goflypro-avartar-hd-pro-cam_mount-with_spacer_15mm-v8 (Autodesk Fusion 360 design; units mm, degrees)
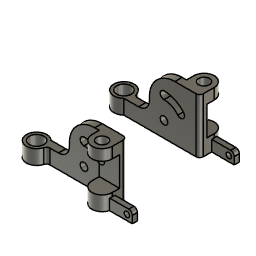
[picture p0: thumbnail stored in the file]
sketch "Skizze1" plane through (0, 0, 0) normal (0, 0, 1) x axis (1, 0, 0)
  line L1 (7.2, 0) -> (-7.2, 0)
  line L2 (7.2, 0) -> (7.2, -2)
  line L3 (-1, 0) -> (-1, 2)
  line L4 (12.8, 2) -> (-8.605, 2)
  line L5 (12.8, 2) -> (12.8, -2)
  line L6 (12.8, 0) -> (7.2, 0)
  line L7 (11, -2) -> (11, 2)
  line L8 (12.8, -2) -> (11, -2)
  circle C1 centre (-10, 0) radius 2
  circle C2 centre (10, -2) radius 1.5
  circle C3 centre (-10, 0) radius 2.8
  circle C4 centre (10, -2) radius 2.8
  point P6 (-7.2, 0)
  point P7 (7.2, -2)
  point P10 (-1, 0)
  point P12 (12.8, -2)
  point P14 (12.8, 0)
  point P15 (11, 2)
  concentric C1 C3
  concentric C2 C4
  coincident C3 P6
  horizontal L1
  coincident C4 P7
  tangent C4 L2
  perpendicular L1 L2
  perpendicular L1 L3
  coincident L1 P10
  coincident C4 P12
  tangent C4 L5
  perpendicular L4 L5
  midpoint L5 P14
  coincident L4 P15
  perpendicular L6 L7
  dimension "d1" diameter C1 = 4
  dimension "d2" diameter C2 = 3
  dimension "d3" diameter C3 = 5.6
  dimension "d4" diameter C4 = 5.6
extrude "Extrusion1" new body sketch "Skizze1" profile of C1 C3 L1 L3 L4 along normal blind 4 bodies "GoFlyPro - Avatar-HD-Pro-cam mount with spacer 15mm - left"
extrude "Extrusion5" new body sketch "Skizze1" profile of C2 C4 L2 L5 L6 L7 L8 along normal blind 4
extrude "Extrusion8" add sketch "Skizze1" profile of C4 L1 L3 L4 L5 L6 L7 along normal blind 15
sketch "Skizze2" plane through (0, 0, 0) normal (0, 1, 0) x axis (1, 0, 0)
  line L1 (7.2, 0) -> (-1, 0)
  line L2 (7.2, -4) -> (7.2, 0)
  line L3 (7.2, -15) -> (7.2, -4)
  line L4 (-1, -15) -> (7.2, -15)
  line L5 (-1, 0) -> (-1, -15)
  circle C1 centre (3, -4.25) radius 1.05
  circle C2 centre (3, -4.25) radius 4.95
  circle C3 centre (3, -4.25) radius 7.05
  circle C4 centre (3, -10.25) radius 1.05
  circle C5 centre (7.5963, -8.1067) radius 1.05
  concentric C1 C2
  concentric C2 C3
  dimension "d8" diameter C1 = 2.1
  dimension "d32" diameter C4 = 2.1
  dimension "d64" diameter C5 = 2.1
extrude "Extrusion2" cut sketch "Skizze2" profile of C1 C2 C3 C4 C5 L3 along normal blind 2
fillet "Abrundung12" radius 1
work_plane "Arbeitsebene" AlongDistance 12
sketch "Skizze3" plane through (0, 0, 15) normal (0, 0, 1) x axis (-1, 0, 0)
  line L1 (-12.8, -2) -> (-12.8, 2)
  line L2 (-7, -2) -> (-12.8, -2)
  line L3 (-7, 0) -> (-7, -2)
  line L4 (-7.2, 0) -> (-7, 0)
  line L5 (-11.9596, 0) -> (-7.2, 0)
  line L6 (1, 0) -> (1, -2)
  line L7 (-7.2, 0) -> (1, 0)
  line L8 (-12.8, 0) -> (-7.2, 0)
  line L9 (-12.8, -2) -> (-12.8, 0)
  line L10 (1, -2) -> (-12.8, -2)
  line L11 (-11.9596, 0) -> (-12.8, 0)
  line L12 (-12.8, 2) -> (-12.8, 0)
  line L13 (-8.0404, 0) -> (-7.2, 0)
  line L14 (-7.2, 2) -> (-7.2, 0)
  circle C1 centre (-10, 2) radius 1.5
  circle C2 centre (-10, 2) radius 2.8
  arc A1 centre (-10, 2) radius 2.8 clockwise from (-11.9596, 0) to (-12.8, 2)
  point P14 (-12.8, 0)
  point P16 (-12.8, 0)
  point P2 (-11.9596, 0)
  point P17 (-11.9596, 0)
  point P18 (-12.8, 0)
  point P3 (-12.8, 2)
  point P19 (-12.8, 2)
  point P13 (-7.2, 0)
  point P20 (-7.2, 0)
  point P21 (-8.0404, 0)
  point P22 (-7.2, 0)
  point P23 (-7.2, 2)
  concentric C1 C2
  coincident P14 P16
  coincident P2 P17
  coincident P14 P18
  coincident P3 P19
  coincident P13 P20
  coincident C2 P21
  coincident L5 P21
  coincident P13 P22
  coincident C2 P23
  tangent C2 L14
  dimension "d77" diameter C1 = 3
  dimension "d78" diameter C2 = 5.6
extrude "Extrusion10" add sketch "Skizze3" profile of L1 C1 C2 L5 A1 L8 L11 L12 L13 L14 against normal blind 3
extrude "Extrusion11" cut sketch "Skizze1" profile of C2 L7 L8 along normal blind 3.2
extrude "Extrusion12" cut sketch "Skizze3" profile of C1 against normal blind 3
combine "Kombinieren"
fillet "Abrundung20" radius 7
fillet "Abrundung21" radius 1
sketch "Skizze4" plane through (0, 0, 0) normal (0, 0, 1) x axis (1, 0, 0)
  line L1 (12.5, -2.7) -> (19, -2.7)
  line L2 (12.5, -1.3) -> (12.5, -2.7)
  line L3 (19, -1.3) -> (12.5, -1.3)
  line L4 (19, -2.7) -> (19, -1.3)
  horizontal L1
  vertical L2
  horizontal L3
  vertical L4
extrude "Extrusion13" add sketch "Skizze4" along normal blind 3
sketch "Skizze5" plane through (0, -2.7, 0) normal (0, -1, 0) x axis (1, 0, 0)
  line L1 (12.7111, 0) -> (12.7111, 3)
  line L2 (19, 0) -> (12.7111, 0)
  line L3 (19, 3) -> (19, 0)
  line L4 (12.7111, 3) -> (19, 3)
  circle C1 centre (17.5, 1.5) radius 0.75
  dimension "d93" diameter C1 = 1.5
extrude "Extrusion14" cut sketch "Skizze5" profile of C1 against normal blind 1.4
fillet "Abrundung22" radius 1
fillet "Abrundung23" radius 3
mirror "Spiegeln" mirrorStitchTolerance 0.1 bodies "GoFlyPro - Avatar-HD-Pro-cam mount with spacer 15mm - right"
named bodies: "GoFlyPro - Avatar-HD-Pro-cam mount with spacer 15mm - left", "GoFlyPro - Avatar-HD-Pro-cam mount with spacer 15mm - right"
